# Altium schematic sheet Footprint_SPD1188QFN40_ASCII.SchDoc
size A4; 项目编号: SPSZ2023-052501A; 项目名称: 三相PFC-2.2KW压机+700W风机
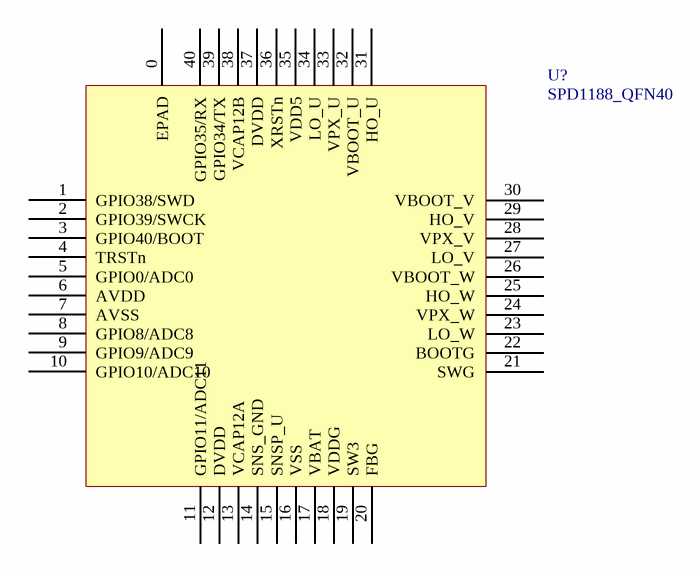
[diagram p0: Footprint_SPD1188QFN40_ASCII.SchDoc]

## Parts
U?  SPD1188_QFN40  [QFN40_WELLS_790-42040-101G]

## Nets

Not connected (* = marked no-connect by the designer): U? 0(EPAD) 1(GPIO38/SWD) 2(GPIO39/SWCK) 3(GPIO40/BOOT) 4(TRSTn) 5(GPIO0/ADC0) 6(AVDD) 7(AVSS) 8(GPIO8/ADC8) 9(GPIO9/ADC9) 10(GPIO10/ADC10) 11(GPIO11/ADC11) 12(DVDD) 13(VCAP12A) 14(SNS_GND) 15(SNSP_U) 16(VSS) 17(VBAT) 18(VDDG) 19(SW3) 20(FBG) 21(SWG) 22(BOOTG) 23(LO_W) 24(VPX_W) 25(HO_W) 26(VBOOT_W) 27(LO_V) 28(VPX_V) 29(HO_V) 30(VBOOT_V) 31(HO_U) 32(VBOOT_U) 33(VPX_U) 34(LO_U) 35(VDD5) 36(XRSTn) 37(DVDD) 38(VCAP12B) 39(GPIO34/TX) 40(GPIO35/RX)

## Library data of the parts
U? = U_SPD1188_QFN40: 32-bit MCU with  Motor Pre-driver and power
